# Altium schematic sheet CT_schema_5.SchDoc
size 259 x 163 mm
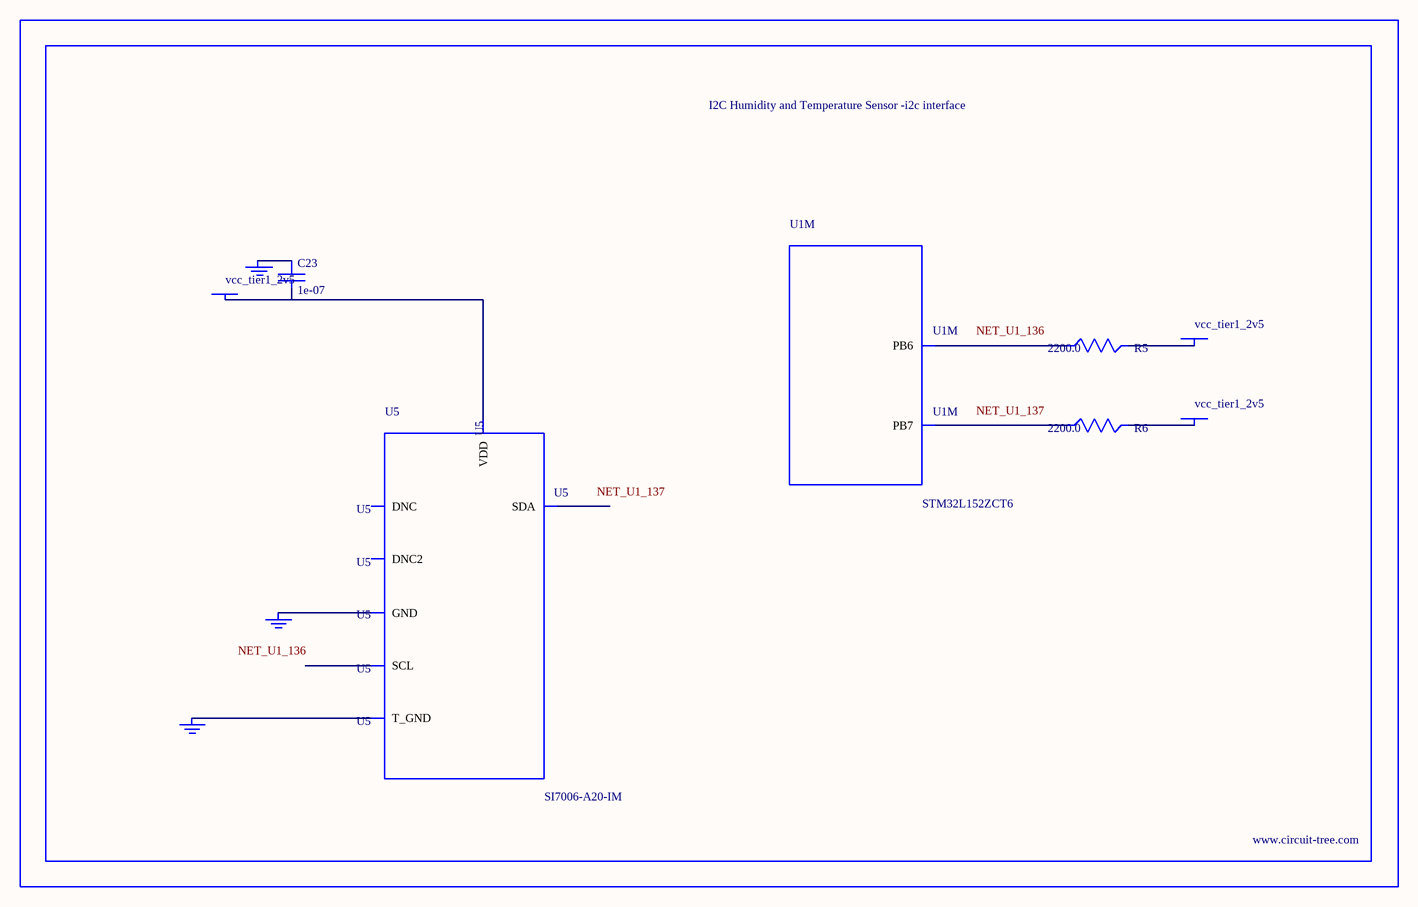
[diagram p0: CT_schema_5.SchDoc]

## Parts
BORDER4  (no value)
C23  1e-07  [C0402]
GND_INSTANCE_4_0  (no value)
GND_INSTANCE_4_1  (no value)
GND_INSTANCE_4_2  (no value)
POWER_INSTANCE_4_0  vcc_tier1_2v5
POWER_INSTANCE_4_1  vcc_tier1_2v5
POWER_INSTANCE_4_2  vcc_tier1_2v5
R5  2200.0  [R0603]
R6  2200.0  [R0603]
U1  STM32L152ZCT6  [LQFP144]  (part M of 13)
U5  SI7006-A20-IM  [DFN-6]

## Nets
NetC23_1: C23.1 GND_INSTANCE_4_0.0(GND)
NetC23_2: C23.2 POWER_INSTANCE_4_0.0(PWR) U5.5(VDD)
NetGND_INSTANCE_4_1_0: GND_INSTANCE_4_1.0(GND) U5.7(T_GND)
NetGND_INSTANCE_4_2_0: GND_INSTANCE_4_2.0(GND) U5.2(GND)
NetPOWER_INSTANCE_4_1_0: POWER_INSTANCE_4_1.0(PWR) R5.2
NetPOWER_INSTANCE_4_2_0: POWER_INSTANCE_4_2.0(PWR) R6.2
NetR5_1: R5.1 U1.136(PB6)
NetR6_1: R6.1 U1.137(PB7)

Not connected (* = marked no-connect by the designer): U5 1(SDA) 3(DNC) 4(DNC2) 6(SCL)

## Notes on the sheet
- Labels drawn without touching a wire or pin: NET_U1_136, NET_U1_137

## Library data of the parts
BORDER4 = BORDER_PAGE4
C23 = C0402C104K3RACTU
GND_INSTANCE_4_0-GND_INSTANCE_4_2 = GND
POWER_INSTANCE_4_0-POWER_INSTANCE_4_2 = PWR
R5 R6 = RC0603JR-072K2L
